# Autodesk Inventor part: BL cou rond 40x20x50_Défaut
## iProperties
Shininess: 64.0
Length Units: 11269
Angle Units: 11279
Time Units: 11290
Mass Units: 11283
Length Display Precision: 3
Angle Display Precision: 2
Compacted: True
Part Number: BL cou rond 40x20x50_Défaut
Document SubType Name: Modeling
Created: 2006-11
Material: Par défaut
Designer: profs_sti
Density: 0.0
Volumn: 0.0
Area: 0.0
PropertySet Name: Model Information
Control State: 0
Master: False
Checked Out: False
Author: profs_sti
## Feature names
1. Base1
